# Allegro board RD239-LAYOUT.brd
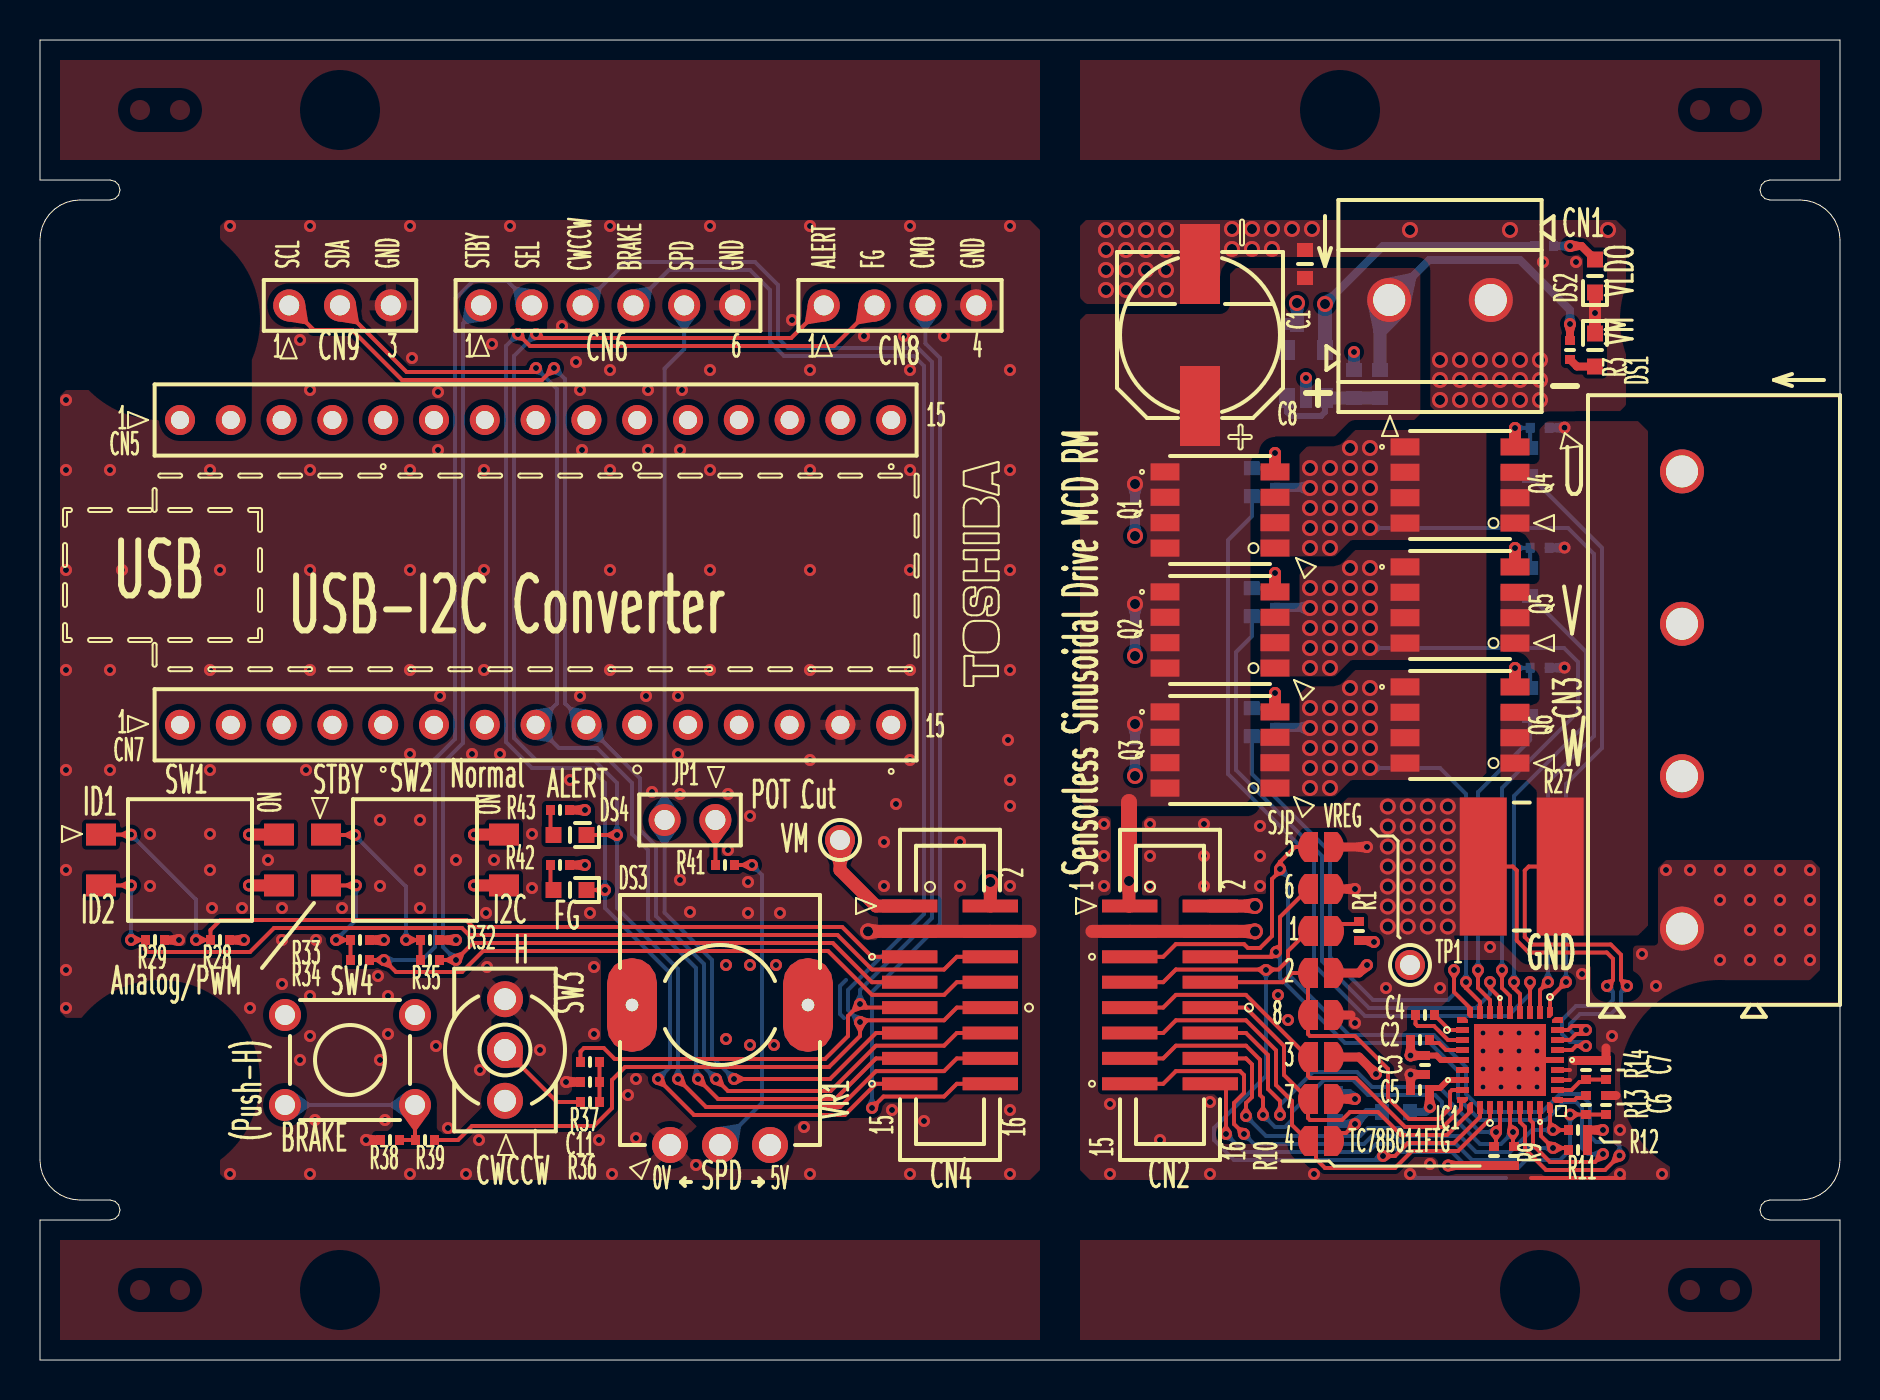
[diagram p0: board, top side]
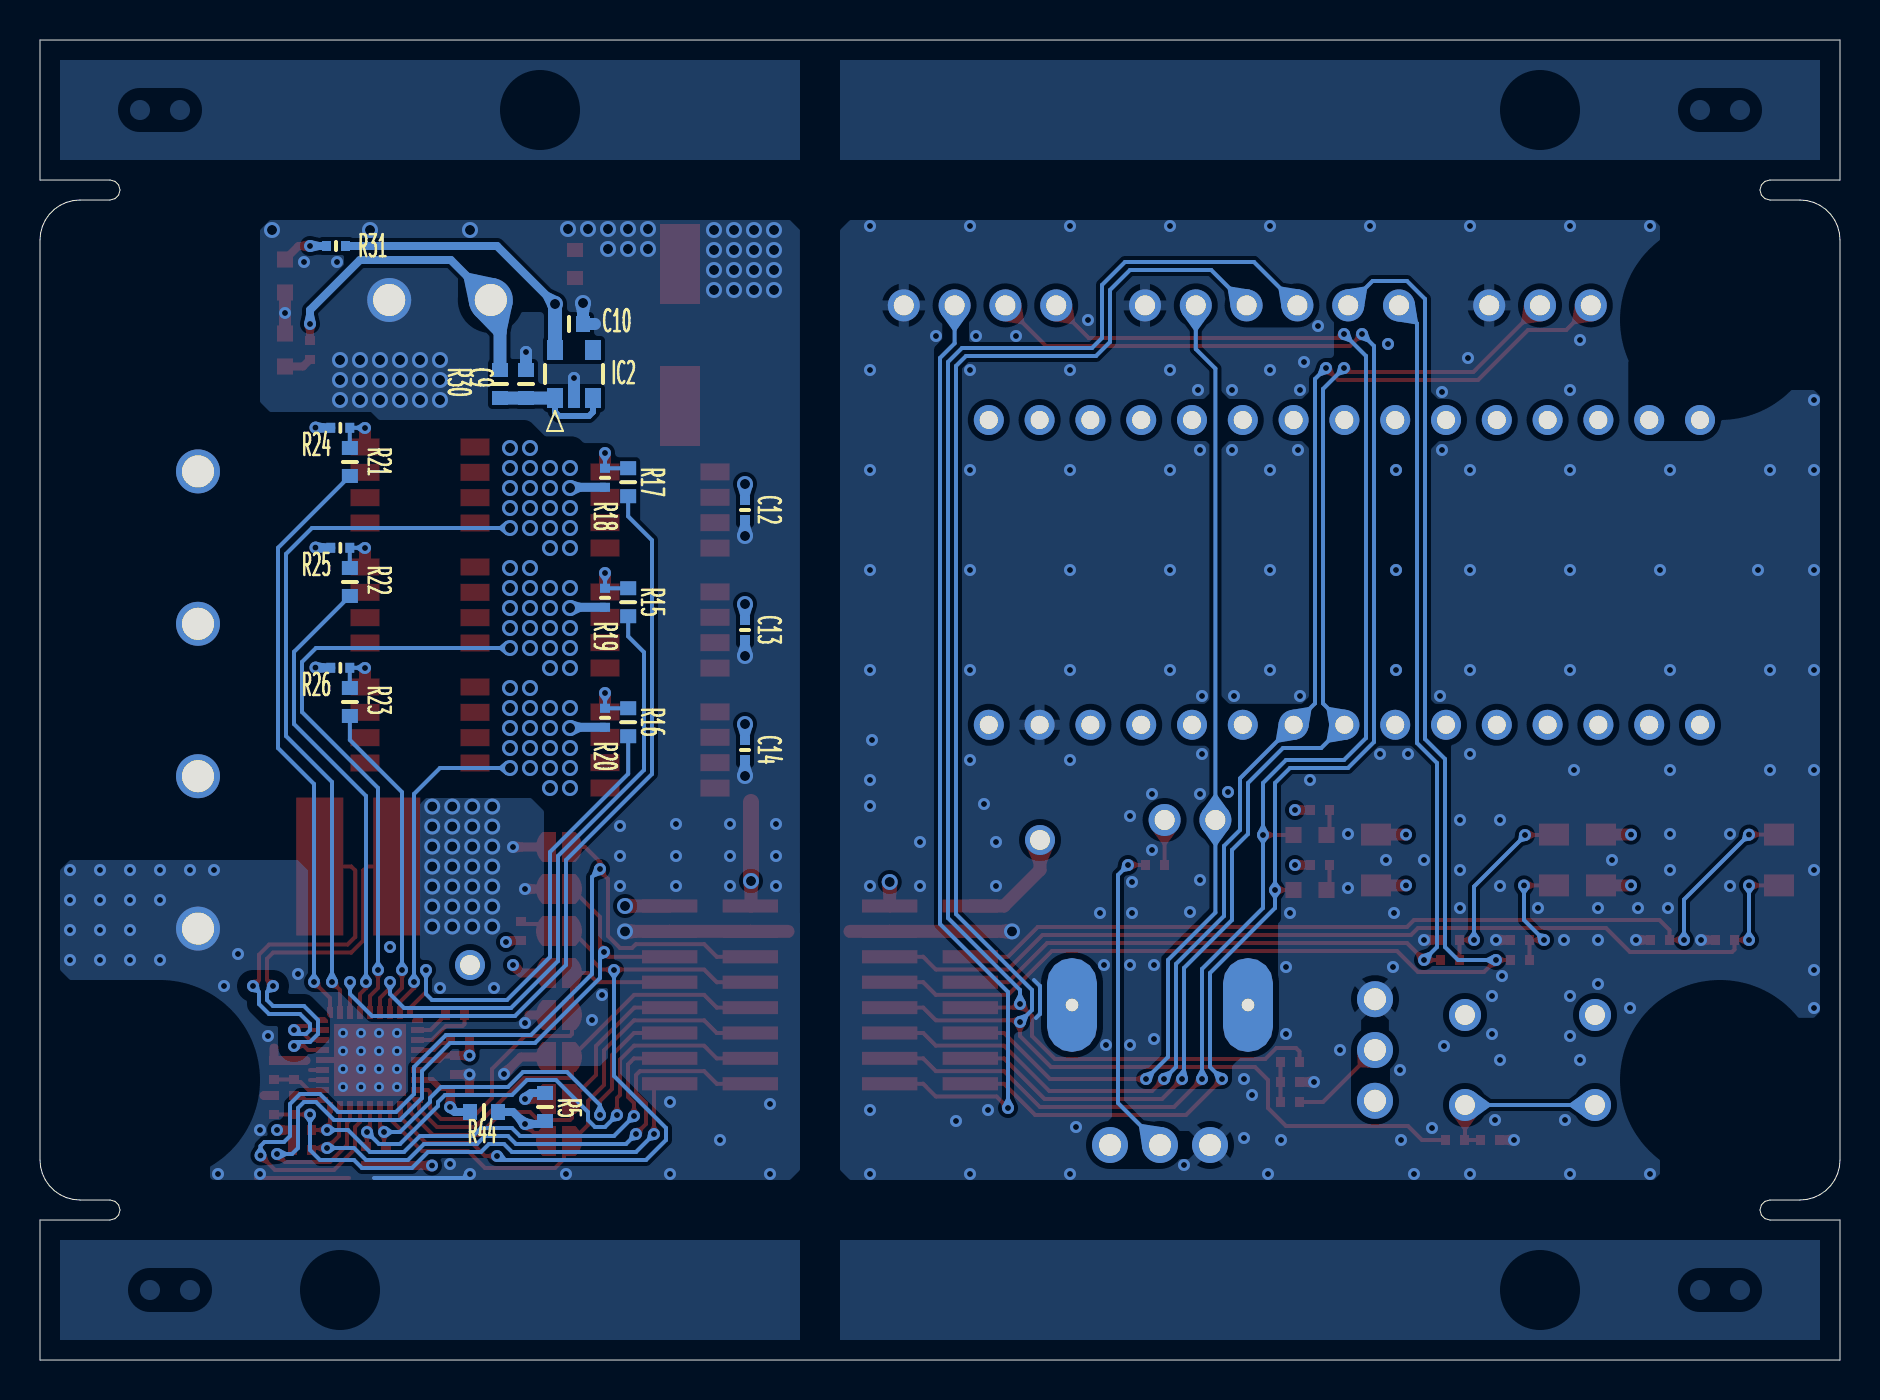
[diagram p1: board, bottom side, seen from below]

Outline 90 x 66 mm; copper layers: TOP, CONDUCTIVE2, CONDUCTIVE3, BOTTOM. Coordinates in mm from the lower left corner of the outline.
Outline path: 0,66 90,66 90,59 86.5,59 86.25,58.93 86.07,58.75 86,58.5 86.07,58.25 86.25,58.07 86.5,58 88,58 88.35,57.97 88.68,57.88 89,57.73 89.29,57.53 89.53,57.29 89.73,57 89.88,56.68 89.97,56.35 90,56 90,10 89.97,9.65 89.88,9.32 89.73,9 89.53,8.71 89.29,8.47 89,8.27 88.68,8.12 88.35,8.03 88,8 86.5,8 86.25,7.93 86.07,7.75 86,7.5 86.07,7.25 86.25,7.07 86.5,7 90,7 90,0 0,0 0,7 3.5,7 3.75,7.07 3.93,7.25 4,7.5 3.93,7.75 3.75,7.93 3.5,8 2,8 1.65,8.03 1.32,8.12 1,8.27 0.71,8.47 0.47,8.71 0.27,9 0.12,9.32 0.03,9.65 0,10 0,56 0.03,56.35 0.12,56.68 0.27,57 0.47,57.29 0.71,57.53 1,57.73 1.32,57.88 1.65,57.97 2,58 3.5,58 3.75,58.07 3.93,58.25 4,58.5 3.93,58.75 3.75,58.93 3.5,59 0,59 0,66

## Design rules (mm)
constraint set DEFAULT: 

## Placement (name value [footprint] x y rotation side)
C1  -  [CHIP1608_GS_1]  63.25 54.8 270 top
C2  -  [CHIP1005_GS_2]  69 16 180 top
C3  -  [CHIP1005_GS_2]  69.25 14.75 90 top
C4  -  [CHIP1005_GS_2]  69.25 17.25 180 top
C5  -  [CHIP1005_GS_2]  69 13.5 0 top
C6  -  [CHIP1005_GS_2]  78.3 12.75 270 top
C7  -  [CHIP1005_GS_2]  78.3 14.5 270 top
C8  -  [AC_S_8X10_2L_PN_A]  58 51.25 0 top
C9  -  [CHIP1608_GS_1]  65.7 48.8 270 bottom
C10  -  [CHIP1608_GS_1]  63.55 51.8 0 bottom
C11  -  [CHIP1005_GS_2]  27.5 13.9 0 top
C12  -  [CHIP1005_GS_2]  54.75 42.5 90 bottom
C13  -  [CHIP1005_GS_2]  54.75 36.5 90 bottom
C14  -  [CHIP1005_GS_2]  54.75 30.5 90 bottom
CN1  -  [TM_I_TB009_508_02_CU_A]  70 53 180 top
CN2  -  [CN_S_3220_16_0300_CNC]  56.5 18.26 270 top
CN3  -  [TM_I_TB005_762_04_CU]  82.1 33 90 top
CN4  -  [CN_S_3220_16_0300_CNC]  45.5 18.26 270 top
CN5  -  [HP_I_6_534237_3_TE]  24.78 47 0 top
CN6  -  [HP_I_M20_99906__HW]  28.4 52.73 0 top
CN7  -  [HP_I_6_534237_3_TE]  24.78 31.76 0 top
CN8  -  [HP_I_M20_99904__HW]  43 52.73 0 top
CN9  -  [HP_I_M20_99903__HW]  15 52.73 0 top
DS1  -  [LD_S_APT1608_KB_A]  77.75 50.5 270 top
DS2  -  [LD_S_APT1608_KB_A]  77.75 54.2 90 top
DS3  -  [LD_S_APT1608_KB_A]  26.5 23.5 180 top
DS4  -  [LD_S_APT1608_KB_A]  26.5 26.25 180 top
IC1  -  [IC_S_QFN_36E_05_GS]  73.5 15 90 top
IC2  -  [IC_S_SOP_5_0_95_TS]  63.3 49.3 180 bottom
JP1  -  [HP_I_M20_99902__HW]  32.5 27 180 top
NOREF  -  []  -13 -22 0 top
NOREF#2  -  []  -13 -18.5 0 top
NOREF#3  -  []  47.9 33.7 90 top
Q1  -  [TR_S_SOP_ADVANCE_TS]  59 42.5 90 top
Q2  -  [TR_S_SOP_ADVANCE_TS]  59 36.5 90 top
Q3  -  [TR_S_SOP_ADVANCE_TS]  59 30.5 90 top
Q4  -  [TR_S_SOP_ADVANCE_TS]  71 43.75 90 top
Q5  -  [TR_S_SOP_ADVANCE_TS]  71 37.75 90 top
Q6  -  [TR_S_SOP_ADVANCE_TS]  71 31.75 90 top
R1  -  [CHIP1005_GS_2]  65.95 21.45 270 top
R3  -  [CHIP1005_GS_2]  76.5 50.5 90 top
R5  -  [CHIP1608_GS_1]  64.75 12.65 270 bottom
R9  -  [CHIP1005_GS_2]  73.7 10.2 270 top
R10  -  [CHIP1005_GS_2]  72.7 10.2 270 top
R11  -  [CHIP1005_GS_2]  76.9 10.5 0 top
R12  -  [CHIP1005_GS_2]  76.9 11.5 0 top
R13  -  [CHIP1005_GS_2]  77.3 12.75 270 top
R14  -  [CHIP1005_GS_2]  77.3 14.5 270 top
R15  -  [CHIP1608_GS_1]  60.59 37.89 90 bottom
R16  -  [CHIP1608_GS_1]  60.59 31.89 90 bottom
R17  -  [CHIP1608_GS_1]  60.59 43.89 90 bottom
R18  -  [CHIP1005_GS_2]  61.75 44.11 90 bottom
R19  -  [CHIP1005_GS_2]  61.75 38.11 90 bottom
R20  -  [CHIP1005_GS_2]  61.75 32.11 90 bottom
R21  -  [CHIP1608_GS_1]  74.51 44.9 90 bottom
R22  -  [CHIP1608_GS_1]  74.51 38.9 90 bottom
R23  -  [CHIP1608_GS_1]  74.51 32.9 90 bottom
R24  -  [CHIP1005_GS_2]  74.99 46.61 180 bottom
R25  -  [CHIP1005_GS_2]  74.99 40.61 0 bottom
R26  -  [CHIP1005_GS_2]  74.99 34.61 180 bottom
R27  -  [R_S_PRL3264_SS]  74.09 24.67 0 top
R28  -  [CHIP1005_GS_2]  9 21 0 top
R29  -  [CHIP1005_GS_2]  5.75 21 0 top
R30  -  [CHIP1608_GS_1]  67 48.8 90 bottom
R31  -  [CHIP1005_GS_2]  75.2 55.7 180 bottom
R32  -  [CHIP1005_GS_2]  19.5 21 0 top
R33  -  [CHIP1005_GS_2]  16 21 0 top
R34  -  [CHIP1005_GS_2]  16 20 180 top
R35  -  [CHIP1005_GS_2]  19.5 20 180 top
R36  -  [CHIP1005_GS_2]  27.5 12.9 180 top
R37  -  [CHIP1005_GS_2]  27.5 14.9 0 top
R38  -  [CHIP1005_GS_2]  17.5 11 0 top
R39  -  [CHIP1005_GS_2]  19.25 11 180 top
R41  -  [CHIP1005_GS_2]  34.25 24.75 0 top
R42  -  [CHIP1005_GS_2]  26 24.75 0 top
R43  -  [CHIP1005_GS_2]  26 27.5 0 top
R44  -  [CHIP1608_GS_1]  67.8 12.4 0 bottom
SJP1  -  [TP_S_SHORTLAND_EC_1_GS_2]  64.05 21.45 0 top
SJP2  -  [TP_S_SHORTLAND_EC_1_GS_2]  64.05 19.35 0 top
SJP3  -  [TP_S_SHORTLAND_EC_1_GS_2]  64.05 15.15 180 top
SJP4  -  [TP_S_SHORTLAND_EC_1_GS_2]  64.05 10.95 180 top
SJP5  -  [TP_S_SHORTLAND_EC_1_GS_2]  64.05 25.65 180 top
SJP6  -  [TP_S_SHORTLAND_EC_1_GS_2]  64.05 23.55 180 top
SJP7  -  [TP_S_SHORTLAND_EC_1_GS_2]  64.05 13.05 180 top
SJP8  -  [TP_S_SHORTLAND_EC_1_GS_2]  64.05 17.25 180 top
SW1  -  [SW_S_DS04_254_2_02BK_SMT_CU]  7.5 25 270 top
SW2  -  [SW_S_DS04_254_2_02BK_SMT_CU]  18.75 25 270 top
SW3  -  [SW_I_2MS1T2B4M2_DW]  23.25 15.5 90 top
SW4  -  [SW_I_6X6TACTILE_GS]  15.5 15 0 top
TP1  -  [TP_I_TH1_0_LC1_5_RC1_6_GS]  68.5 19.75 0 top
VM  -  [TP_I_TH1_0_LC1_5_RC1_6_GS]  40 26 0 top
VR1  -  [VR_I_PTV09A_4020U_B_BO]  34 17.75 0 top

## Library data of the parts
C1 C9 C10 R5 R15-R17 R21-R23 R30 R44 = Chip1608_GS_1
C2-C7 C11-C14 R1 R3 R9-R14 R18-R20 R24-R26 R28 R29 R31-R39 R41-R43 = Chip1005_GS_2
C8 = EEE-FN1V331UP_PN_A
CN1 = TB009-508-02_CU_A
CN2 CN4 = 3220-16-0300_CNC
CN3 = TB005-762-04_CU
CN5 CN7 = 6-534237-3_TE
CN6 = M20-99906**_HW
CN8 = M20-99904**_HW
CN9 = M20-99903**_HW
DS1-DS4 = APT1608_KB_A
IC1 = TC78B011FTG_GS
IC2 = TCR1HF_TS
JP1 = M20-99902**_HW
Q1-Q6 = TPH1R204PB_TS
R27 = PRL3264_SS
SJP1-SJP8 = TP_S_ShortLand_EC-1_GS
SW1 SW2 = DS04-254-2-02BK-SMT_CU
SW3 = 2MS1T2B4M2_DW
SW4 = B3F-1025_GS
TP1 VM = TP_I_TH1.0_LC1.5_RC1.6_GS
VR1 = PTV09A-4020U-B_BO

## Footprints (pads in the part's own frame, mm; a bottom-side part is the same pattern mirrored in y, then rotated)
AC_S_8X10_2L_PN_A
  rect 2x4 smd: 1(0,3.55) 2(0,-3.55)
CHIP1005_GS_2
  rect 0.45x0.5 smd: 1(-0.475,0) 2(0.475,0)
CHIP1608_GS_1
  rect 0.7x0.8 smd: 1(-0.7,0) 2(0.7,0)
CN_S_3220_16_0300_CNC
  rect 0.65x2.77 smd: 1(-4.445,-2.015) 2(-4.445,2.015) 3(-3.175,-2.015) 4(-3.175,2.015) 5(-1.905,-2.015) 6(-1.905,2.015) 7(-0.635,-2.015) 8(-0.635,2.015) 9(0.635,-2.015) 10(0.635,2.015) 11(1.905,-2.015) 12(1.905,2.015) 13(3.175,-2.015) 14(3.175,2.015) 15(4.445,-2.015) 16(4.445,2.015)
HP_I_6_534237_3_TE
  round 1.5 hole 0.9: 1(-17.78,0) 2(-15.24,0) 3(-12.7,0) 4(-10.16,0) 5(-7.62,0) 6(-5.08,0) 7(-2.54,0) 8(0,0) 9(2.54,0) 10(5.08,0) 11(7.62,0) 12(10.16,0) 13(12.7,0) 14(15.24,0) 15(17.78,0)
HP_I_M20_99902__HW
  round 1.6 hole 1: 1(-1.27,0) 2(1.27,0)
HP_I_M20_99903__HW
  round 1.6 hole 1: 1(-2.54,0) 2(0,0) 3(2.54,0)
HP_I_M20_99904__HW
  round 1.6 hole 1: 1(-3.81,0) 2(-1.27,0) 3(1.27,0) 4(3.81,0)
HP_I_M20_99906__HW
  round 1.6 hole 1: 1(-6.35,0) 2(-3.81,0) 3(-1.27,0) 4(1.27,0) 5(3.81,0) 6(6.35,0)
IC_S_QFN_36E_05_GS
  custom 0.075x0.075 smd: 1(-2,-2.375) 9(2,-2.375) 10(2.375,-2) 18(2.375,2) 19(2,2.375) 27(-2,2.375) 28(-2.375,2) 36(-2.375,-2)
  rect 0.3x0.65 smd: 2(-1.5,-2.375) 3(-1,-2.375) 4(-0.5,-2.375) 5(0,-2.375) 6(0.5,-2.375) 7(1,-2.375) 8(1.5,-2.375) 20(1.5,2.375) 21(1,2.375) 22(0.5,2.375) 23(0,2.375) 24(-0.5,2.375) 25(-1,2.375) 26(-1.5,2.375)
  rect 0.65x0.3 smd: 11(2.375,-1.5) 12(2.375,-1) 13(2.375,-0.5) 14(2.375,0) 15(2.375,0.5) 16(2.375,1) 17(2.375,1.5) 29(-2.375,1.5) 30(-2.375,1) 31(-2.375,0.5) 32(-2.375,0) 33(-2.375,-0.5) 34(-2.375,-1) 35(-2.375,-1.5)
  rect 3.6x3.6 smd: 37(0,0)
IC_S_SOP_5_0_95_TS
  rect 0.8x1 smd: 1(-0.95,-1.2) 3(0.95,-1.2) 4(0.95,1.2) 5(-0.95,1.2)
  rect 0.6x1 smd: 2(0,-1.2)
LD_S_APT1608_KB_A
  rect 0.8x0.8 smd: 1(0.825,0) 2(-0.825,0)
R_S_PRL3264_SS
  rect 2.35x6.9 smd: 1(-1.925,0) 2(1.925,0)
SW_I_2MS1T2B4M2_DW
  round 1.8 hole 1.1: 1(-2.54,0) 2(0,0) 3(2.54,0)
SW_I_6X6TACTILE_GS
  round 1.6 hole 1: 1(3.25,-2.25) 2(-3.25,-2.25) 3(3.25,2.25) 4(-3.25,2.25)
SW_S_DS04_254_2_02BK_SMT_CU
  rect 1.1x1.5 smd: 1(-1.27,-4.45) 2(1.27,-4.45) 3(1.27,4.45) 4(-1.27,4.45)
TM_I_TB005_762_04_CU
  round 2.2 hole 1.6: 1(11.43,0) 2(3.81,0) 3(-3.81,0) 4(-11.43,0)
TM_I_TB009_508_02_CU_A
  round 2.2 hole 1.6: 1(2.54,0) 2(-2.54,0)
TP_I_TH1_0_LC1_5_RC1_6_GS
  round 1.5 hole 1: 1(0,0)
TP_S_SHORTLAND_EC_1_GS_2
  custom 0.25x0.25 smd: 1(-0.65,0) 2(0.65,0)
TR_S_SOP_ADVANCE_TS
  rect 0.85x1.45 smd: 1(-1.905,-2.75) 2(-0.635,-2.75) 3(0.635,-2.75) 4(1.905,-2.75) 5(1.905,2.75) 6(0.635,2.75) 7(-0.635,2.75) 8(-1.905,2.75)
VR_I_PTV09A_4020U_B_BO
  round 1.8 hole 1.1: 1(-2.5,-7) 2(0,-7) 3(2.5,-7)
  custom 0.625x0.625 hole 1.9x4.1: 4(-4.4,0) 5(4.4,0)

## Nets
GND: C1.1 C3.1 C5.1 C6.1 C7.1 C8.1 C9.1 C10.1 C12.1 C13.1 C14.1 CN1.2 CN2.3 CN2.4 CN3.4 DS1.2 DS2.2 IC1.3 IC1.4 IC1.5 IC1.6 IC1.37 IC2.2 R5.1 R14.1 R27.1 SJP3.1 SJP5.1 SJP6.1 SJP7.1 SJP8.1
GNDX: C11.1 CN4.3 CN4.4 CN6.6 CN7.14 CN8.4 CN9.3 R28.2 R29.2 R32.2 R33.2 R38.1 SW3.3 VR1.1
ALERT: CN2.14 IC1.36 R12.1
ALERTX: CN4.14 CN8.1 DS4.2
BRAKE: CN2.10 IC1.28 SJP7.2
BRAKEX: CN4.10 CN6.4 R39.1
CMO: C6.2 CN2.16 R13.2
CMOX: CN4.16 CN8.3
CWCCW: CN2.9 IC1.27 SJP3.2
CWCCWX: CN4.9 CN6.3 R37.1
FG: CN2.15 IC1.35 R11.1
FGX: CN4.15 CN8.2 DS3.2
GHU: IC1.12 R17.1
GHV: IC1.15 R15.1
GHW: IC1.18 R16.1
GLU: IC1.10 R21.1
GLV: IC1.13 R22.1
GLW: IC1.16 R23.1
ID1: CN2.5 IC1.33 SJP5.2
ID1X: CN4.5 R28.1 SW1.1
ID2: CN2.6 IC1.34 SJP6.2
ID2X: CN4.6 R29.1 SW1.2
OUTU: CN3.1 IC1.11 Q1.1 Q1.2 Q1.3 Q4.5 Q4.6 Q4.7 Q4.8 R18.1
OUTV: CN3.2 IC1.14 Q2.1 Q2.2 Q2.3 Q5.5 Q5.6 Q5.7 Q5.8 R19.1
OUTW: CN3.3 IC1.17 Q3.1 Q3.2 Q3.3 Q6.5 Q6.6 Q6.7 Q6.8 R20.1
RSA: IC1.7 IC1.8 Q4.1 Q4.2 Q4.3 Q5.1 Q5.2 Q5.3 Q6.1 Q6.2 Q6.3 R24.1 R25.2 R26.1 R27.2
SCL: CN2.12 IC1.31 R10.1
SCLX: CN4.12 CN7.9 CN9.1
SDA: CN2.13 IC1.32 R9.1
SDAX: CN4.13 CN7.8 CN9.2
SEL: CN2.8 IC1.26 SJP2.1 SJP8.2
SELX: CN4.8 CN6.2 R34.1
SPD: CN2.11 IC1.30 SJP4.2
SPDX: CN4.11 CN6.5 JP1.2
STBY: CN2.7 IC1.29 SJP1.1
STBYX: CN4.7 CN6.1 R35.1
VLDO: C10.2 CN2.2 IC2.5 R1.2 R31.2
VLDOX: CN4.2 R42.2 R43.2 SW1.3 SW1.4 SW2.3 SW2.4 SW3.1 SW4.3 SW4.4 VR1.3
VM: C1.2 C2.2 C3.2 C8.2 C12.2 C13.2 C14.2 CN1.1 CN2.1 IC1.23 Q1.5 Q1.6 Q1.7 Q1.8 Q2.5 Q2.6 Q2.7 Q2.8 Q3.5 Q3.6 Q3.7 Q3.8 R3.2 R30.2
VMX: CN4.1 VM.1
VREG: C5.2 IC1.25 R9.2 R10.2 R11.2 R12.2 R44.2 SJP2.2 TP1.1
N00000: CN5.1
N73073: C4.1 IC1.20
N73078: C4.2 IC1.21
N73366: C7.2 IC1.2 R14.2
N87798: Q1.4 R17.2 R18.2
N87832: Q2.4 R15.2 R19.2
N87866: Q3.4 R16.2 R20.2
N88470: Q5.4 R22.2 R25.1
N88482: Q6.4 R23.2 R26.2
N88708: Q4.4 R21.2 R24.2
N99829: C2.1 IC1.22
N100688: IC1.1 R13.1
N145122: R1.1 SJP1.2
N153811: R32.1 R35.2 SW2.1
N153813: R33.1 R34.2 SW2.2
N153829: C11.2 R36.1 R37.2
N153845: R38.2 R39.2 SW4.1 SW4.2
N153865: R41.2 VR1.2
N153867: JP1.1 R41.1
N157910: R5.2 R44.1 SJP4.1
N213336: R36.2 SW3.2
N213555: DS1.1 R3.1
N213849: DS3.1 R42.1
N213908: DS4.1 R43.1
N228706: C9.2 IC2.1 IC2.3 R30.1
N228786: DS2.1 R31.1

Pads without a net: CN5 2 3 4 5 6 7 8 9 10 11 12 13 14 15; CN7 1 2 3 4 5 6 7 10 11 12 13 15; IC1 9 19 24; IC2 4; VR1 4 5

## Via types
v1: diameter 0.6, hole 0.3, TOP to BOTTOM, 311 vias
v2: diameter 0.8, hole 0.5, TOP to BOTTOM, 146 vias
v3: diameter 0.5, hole 0.25, TOP to BOTTOM, 16 vias

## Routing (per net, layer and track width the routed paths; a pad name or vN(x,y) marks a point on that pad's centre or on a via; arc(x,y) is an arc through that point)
GND: length 59.5
  TOP w0.2: 75.92,14.5 76.5,14.5 ; 74.55,9.1 79.2,9.1 ; 75.92,14 76.5,14 ; 75.92,15.5 76.6,15.5 76.8,15.7 v1(77.3,15.7) ; v1(78.35,18.7) 78.65,19 78.65,20.06 78.34,20.37 74.44,20.37 73.84,20.97 73.84,24.47 73.64,24.67 R27.1
  TOP w0.3: 75.04,15 IC1.5 75.92,15
  TOP w0.45: SJP5.1 v1(66.35,25.65) ; 65.55,17.25 SJP8.1 ; SJP3.1 65.95,15.15 v1(66.8,14.3) ; 76.7,14.97 R14.1 C7.1 78.3,15.6 ; C6.1 78.8,13.22 ; SJP7.1 v1(65.75,13.05) ; C5.1 v1(68.53,14.28) C3.1 ; SJP6.1 v1(65.75,23.55)
  TOP w0.6: DS2.2 v1(77.75,52.35) DS1.2
  TOP w0.65: 52.6,21.43 CN2.3 CN2.4 v2(60.75,21.43)
  BOTTOM w0.2: v1(78.35,18.7) 78.65,18.4 78.65,18 78.35,17.7 76.8,17.7 76.1,17 76.1,16.3 76.5,15.9 77,15.9 v1(77.3,15.7) ; 73.3,9.1 68.8,9.1 v1(68.5,9.3)
  BOTTOM w0.4: v1(65.75,13.05) 65.45,13.35 R5.1
  BOTTOM w0.45: C12.1 v2(54.75,41.2) ; C13.1 v2(54.75,35.2) ; C14.1 v2(54.75,29.2)
  BOTTOM w0.6: v2(62.85,52.85) C10.1 62.25,51.8 ; IC2.2 v1(63.3,49.1) ; C9.1 v1(65.7,50.4)
  vias: v1(53.2,26.8) v1(53.2,25.2) v1(53.2,23.7) v1(53.5,12.8) v1(53.5,9.3) v1(55.5,26.8) v1(55.5,25.2) v1(55.5,23.7) v1(56,11) v1(58.2,26.8) v1(58.2,25.2) v1(58.2,23.7) v1(58.5,12.9) v1(58.5,9.3) v1(61,26.7) v1(61,25.2) v1(61,23.7) v1(61.9,18.25) v1(62.4,17) v1(63.7,9.3) v1(65.75,16.85) v1(67.3,18.6) v1(69.5,9.8) v1(70,18.6) v1(72.5,20.65) v1(75.15,54.9) v1(76.8,54.9) v1(77.1,19.3) v1(78.6,16.2) v1(79,11.5) v1(79,9.3) v1(80.1,20.3) v1(80.8,18.7) v1(81.1,9.3) v1(81.3,24.5) v1(82.5,24.5) v1(84,24.5) v1(84,23) v1(84,20) v1(85.5,24.5) v1(85.5,23) v1(85.5,21.5) v1(85.5,20) v1(87,24.5) v1(87,23) v1(87,21.5) v1(87,20) v1(88.5,24.5) v1(88.5,23) v1(88.5,21.5) v1(88.5,20) v2(53.3,56.5) v2(53.3,55.5) v2(53.3,54.5) v2(53.3,53.5) v2(54.3,56.5) v2(54.3,55.5) v2(54.3,54.5) v2(54.3,53.5) v2(55.3,56.5) v2(55.3,55.5) v2(55.3,54.5) v2(55.3,53.5) v2(56.3,56.5) v2(56.3,55.5) v2(56.3,54.5) v2(56.3,53.5) v2(59.6,56.55) v2(59.6,55.55) v2(60.6,56.55) v2(60.6,55.55) v2(61.6,56.55) v2(61.6,55.55) v2(62.6,56.55) v2(63.6,56.55) v2(67.39,27.67) v2(67.39,26.67) v2(67.39,25.67) v2(67.39,24.67) v2(67.39,23.67) v2(67.39,22.67) v2(67.39,21.67) v2(68.39,27.67) v2(68.39,26.67) v2(68.39,25.67) v2(68.39,24.67) v2(68.39,23.67) v2(68.39,22.67) v2(68.39,21.67) v2(68.5,56.5) v2(69.39,27.67) v2(69.39,26.67) v2(69.39,25.67) v2(69.39,24.67) v2(69.39,23.67) v2(69.39,22.67) v2(69.39,21.67) v2(70,50) v2(70,49) v2(70,48) v2(70.39,27.67) v2(70.39,26.67) v2(70.39,25.67) v2(70.39,24.67) v2(70.39,23.67) v2(70.39,22.67) v2(70.39,21.67) v2(71,50) v2(71,49) v2(71,48) v2(72,50) v2(72,49) v2(72,48) v2(73,50) v2(73,49) v2(73,48) v2(73.5,56.5) v2(74,50) v2(74,49) v2(74,48) v2(75,50) v2(75,49) v2(75,48) v2(78.4,56.5) v3(72.15,16.35) v3(72.15,15.45) v3(72.15,14.55) v3(72.15,13.65) v3(73.05,16.35) v3(73.05,15.45) v3(73.05,14.55) v3(73.05,13.65) v3(73.95,16.35) v3(73.95,15.45) v3(73.95,14.55) v3(73.95,13.65) v3(74.85,16.35) v3(74.85,15.45) v3(74.85,14.55) v3(74.85,13.65)
GNDX: length 15.5
  TOP w0.45: R38.1 v1(16.3,11) ; R28.2 v1(10.2,21) ; C11.1 v1(26.3,13.9) ; R32.2 v1(20.8,21) ; R33.2 v1(17.2,21) ; R29.2 v1(6.95,21)
  TOP w0.65: v2(41.4,21.43) CN4.3 CN4.4 49.5,21.43
  CONDUCTIVE3 w0.2: 22.85,14.25 23.7,14.25
  BOTTOM w0.2: 40.2,17.1 40,17.3 40,18.7 40.3,19
  vias: v1(1.3,48) v1(1.3,44.5) v1(1.3,39.5) v1(1.3,34.5) v1(1.3,29.5) v1(1.3,24.5) v1(1.3,19.5) v1(1.3,17.6) v1(3.5,44.5) v1(3.5,34.5) v1(3.5,29.5) v1(4.1,39.5) v1(5.5,26.3) v1(5.5,23.7) v1(8.5,44.5) v1(8.5,34.5) v1(8.5,29.5) v1(8.5,26.3) v1(8.5,24.5) v1(8.6,22.6) v1(9,39.5) v1(9.5,56.7) v1(9.5,9.3) v1(10.1,22.6) v1(10.5,17.6) v1(11.4,25) v1(12.1,22.6) v1(12.1,21) v1(12.1,18.8) v1(13,51) v1(13,15) v1(13.3,29.5) v1(13.5,56.7) v1(13.5,48.5) v1(13.5,44.5) v1(13.5,39.5) v1(13.5,34.5) v1(13.5,18.2) v1(13.5,16.2) v1(13.5,9.3) v1(13.8,21) v1(13.75,12) v1(15.1,22.6) v1(16.9,19.2) v1(17,27) v1(17,23.7) v1(17,15) v1(17.25,12) v1(17.4,18.2) v1(17.4,16.3) v1(18.5,56.7) v1(18.5,44.5) v1(18.5,39.5) v1(18.5,34.5) v1(18.5,30.3) v1(18.5,9.3) v1(18.6,50.1) v1(19,27) v1(19,24.5) v1(19,22.6) v1(19.8,15.7) v1(19.9,48.4) v1(19.9,45.5) v1(20,33.2) v1(20.4,11.6) v1(20.8,25) v1(21.3,9.3) v1(21.6,30.3) v1(21.95,11) v1(22,14.5) v1(22.2,44.5) v1(22.2,39.5) v1(22.2,34.5) v1(22.3,22.35) v1(22.35,19.65) v1(22.6,50.8) v1(22.7,25) v1(23,30.3) v1(23.5,56.7) v1(24.6,26.3) v1(24.6,23.6) v1(25,15.5) v1(26.1,51.7) v1(26.5,29) v1(26.8,49.9) v1(27,48.5) v1(27,33.2) v1(27.1,45.5) v1(27.5,22.35) v1(27.7,19.65) v1(27.7,16.3) v1(27.95,11) v1(28.5,56.7) v1(28.5,49.5) v1(28.5,44.5) v1(28.5,39.5) v1(28.5,34.5) v1(28.6,9.3) v1(29.4,13.25) v1(29.8,14.05) v1(29.8,11.1) v1(30.3,33.2) v1(30.4,48.5) v1(30.4,45.5) v1(30.6,28.4) v1(31.9,33.2) v1(31.9,30.3) v1(32,45.5) v1(32,28.3) v1(32,24) v1(32.1,48.5) v1(32.5,22.4) v1(32.8,9.75) v1(33.5,56.7) v1(33.5,49.5) v1(33.5,44.5) v1(33.5,39.5) v1(33.5,34.5) v1(34.3,19.75) v1(34.3,16.05) v1(34.4,28.3) v1(34.4,25.5) v1(35.4,23.9) v1(35.4,22.35) v1(35.5,27.2) v1(35.5,19.75) v1(35.5,15.75) v1(36.7,15.75) v1(36.8,19.75) v1(37,22.35) v1(37.6,52) v1(38.2,11.65) v1(38.5,56.7) v1(38.5,49.5) v1(38.5,44.5) v1(38.5,39.5) v1(38.5,34.5) v1(38.5,30) v1(38.5,9.3) v1(41.2,51.2) v1(42.2,25.9) v1(42.2,23.7) v1(42.6,12.5) v1(42.8,27.8) v1(43.2,51.2) v1(43.5,56.7) v1(43.5,49.5) v1(43.5,44.5) v1(43.5,39.5) v1(43.5,34.5) v1(43.5,30) v1(43.5,9.3) v1(44.2,11.95) v1(45.2,51.2) v1(46,25.9) v1(46,23.7) v1(48.4,31) v1(48.5,56.7) v1(48.5,49.5) v1(48.5,44.5) v1(48.5,39.5) v1(48.5,34.5) v1(48.5,29) v1(48.5,27.7) v1(48.5,23.7) v1(48.5,12.5) v1(48.5,9.3)
ALERT: length 23.7
  TOP w0.2: 76.42,11.5 v1(75.65,11.5) 75.5,11.83 75.5,12.57 ; v1(60.3,12.2) 60.3,12.85 60.6,13.15 60.6,14.78 60.3,15.08 CN2.14
  BOTTOM w0.2: v1(75.65,11.5) 74.6,11.5 73.5,10.4 71.8,10.4 71,11.2 68.35,11.2 67.95,11.6 66.4,11.6 66,11.2 61.3,11.2 v1(60.3,12.2)
ALERTX: length 76.7
  TOP w0.2: CN8.1 37.56,51.1 25.1,51.1 v1(24.8,51.3) ; DS4.2 v1(28.85,26.25) ; v1(31.9,14.05) 33.3,12.65 40.01,12.65 41.8,14.45 45.2,14.45 45.84,15.08 CN4.14
  BOTTOM w0.2: v1(24.8,51.3) 23.7,50.2 23.7,31.1 24.8,30 27.7,30 28.85,28.85 v1(28.85,26.25) 28.85,22.6 31.9,19.55 v1(31.9,14.05)
BRAKE: length 18
  TOP w0.2: CN2.10 60.28,17.62 62.2,15.7 62.2,14.25 SJP7.2 63.4,12.1 63.5,12 65.1,12 65.5,12.4 66.9,12.4 68.05,11.25 70.35,11.25 71.5,12.4 71.5,12.57
BRAKEX: length 85.1
  TOP w0.2: R39.1 20.9,11 21.6,11.7 27.7,11.7 28.6,12.6 28.6,14 29.25,14.65 39.45,14.65 41,16.2 v1(41,16.9) 41.35,16.98 45.2,16.98 45.84,17.62 CN4.10
  BOTTOM w0.2: CN6.4 31.44,54.5 35.5,54.5 36.5,53.5 36.5,50.9 37.2,50.2 43.7,50.2 44.2,49.7 44.2,22.3 40.4,18.5 40.4,17.5 v1(41,16.9)
CMO: length 25.5
  TOP w0.2: v1(76.5,12.28) R13.2 C6.2 ; v1(59.3,11.3) 59.3,13.81 CN2.16
  BOTTOM w0.2: v1(59.3,11.3) 60.2,10.4 66.4,10.4 66.8,10.8 67.55,10.8 67.95,10.4 70.6,10.4 71.4,9.6 73.9,9.6 74.3,10 76,10 76.5,10.5 v1(76.5,12.28)
CMOX: length 48.3
  TOP w0.2: CN4.16 45.84,13.81 45.2,13.18 42.17,13.18 v1(41.6,12.6)
  BOTTOM w0.2: CN8.3 44.27,50.83 45,50.1 45,21.8 41.6,18.4 v1(41.6,12.6)
CWCCW: length 21
  TOP w0.2: 71.08,13 71.05,12.97 71.05,12.55 70.15,11.65 68.25,11.65 65.8,14.1 63.5,14.1 63.4,14.2 SJP3.2 60.3,18.26 56.8,18.26 56.16,17.62 CN2.9
CWCCWX: length 74.5
  TOP w0.2: CN4.9 41.31,17.62 v1(41,17.8) 40.4,17.2 40.4,16.2 39.25,15.05 28.74,15.05 28.19,15.6 27.2,15.6 27.02,15.43 27.02,15
  BOTTOM w0.2: v1(41,17.8) 41,18.5 44.6,22.1 44.6,49.9 43.9,50.6 37.4,50.6 36.9,51.1 36.9,53.75 35.75,54.9 29.3,54.9 CN6.3
FG: length 29
  TOP w0.2: 75,12.57 75,12.05 75.05,12 75.05,11.2 v1(75.65,10.6) 76.33,10.6 76.42,10.5 ; v1(60.2,11.3) 59.7,11.8 59.7,12.85 60.2,13.35 60.2,14.25 60,14.45 56.8,14.45 56.16,13.81 CN2.15
  BOTTOM w0.2: v1(75.65,10.6) 74.3,10.6 73.7,10 71.6,10 70.8,10.8 68.15,10.8 67.75,11.2 66.6,11.2 66.2,10.8 60.7,10.8 v1(60.2,11.3)
FGX: length 76.7
  TOP w0.2: v1(30.9,14.05) 32.7,12.25 40.24,12.25 41.8,13.81 CN4.15 ; DS3.2 v1(28.25,23.5) ; v1(23.9,51.3) 24.5,50.7 39.7,50.7 CN8.2
  BOTTOM w0.2: v1(23.9,51.3) 23.3,50.7 23.3,30.9 24.6,29.6 27.5,29.6 28.25,28.85 v1(28.25,23.5) 28.25,22.6 31.5,19.35 31.5,14.65 v1(30.9,14.05)
GHU: length 40.1
  TOP w0.2: 74.5,17.43 v1(74.5,18.9)
  BOTTOM w0.2: v1(74.5,18.9) 74.5,18.3 73.4,17.2 66.25,17.2 63.7,19.75 63.7,25 59.4,29.3 59.4,40.99 60.59,42.18 60.59,43.19
GHV: length 31.3
  TOP w0.2: 73,17.43 73,18.1 72.5,18.6 v1(72.5,18.9)
  BOTTOM w0.2: v1(72.5,18.9) 72.5,18.3 71.8,17.6 66.45,17.6 64.1,19.95 64.1,25.2 59.8,29.5 59.8,35.39 60.59,36.18 R15.1
GHW: length 23.5
  TOP w0.2: 71.5,17.43 71.5,17.6 70.7,18.4 v1(70.7,19.5)
  BOTTOM w0.2: v1(70.7,19.5) 70.7,18.3 70.4,18 66.65,18 64.5,20.15 64.5,25.4 60.59,29.31 R16.1
GLU: length 29.3
  TOP w0.2: v1(76.3,18.9) 75.5,18.1 75.5,17.43
  BOTTOM w0.2: v1(76.3,18.9) 76.3,28.8 78.1,30.6 78.1,40.61 R21.1
GLV: length 23.5
  TOP w0.2: 74,17.43 74,18.3 73.7,18.6 v1(73.7,18.9)
  BOTTOM w0.2: R22.1 77.3,35.41 77.3,31.8 73.7,28.2 v1(73.7,18.9)
GLW: length 16.1
  TOP w0.2: 72.5,17.43 72.5,18 71.9,18.6 v1(71.9,19.5)
  BOTTOM w0.2: v1(71.9,19.5) 71.9,28.39 74.51,31 R23.1
ID1: length 49.4
  TOP w0.2: CN2.5 56.16,20.16 56.8,20.8 60.2,20.8 60.4,20.6 61,20.6 61.6,21.2 61.6,24.05 61.8,24.25 v1(62,24.55) 62,24.9 62.75,25.65 SJP5.2 ; v1(78.97,10.22) 78.25,9.5 75.3,9.5 74.25,10.55 74.25,11.65 74,11.9 74,12.57
  BOTTOM w0.2: v1(78.97,10.22) 78.97,10.7 78.78,10.9 77.8,10.9 77.5,11.2 77.5,12.8 77,13.3 76,13.3 75.1,12.4 72.2,12.4 71.3,13.3 71.3,14.65 69.7,16.25 65.45,16.25 62.4,19.3 62.4,24.15 v1(62,24.55)
ID1X: length 45.3
  TOP w0.2: CN4.5 41.6,20.16 40.11,21.65 21.65,21.65 21.3,22 9.03,22 8.53,21.5 R28.1 v1(7.8,21) ; SW1.1 v1(4.55,26.27)
  BOTTOM w0.2: v1(4.55,26.27) 7.8,23.02 v1(7.8,21)
ID2: length 36.9
  TOP w0.2: SJP6.2 62,22.15 62,20.7 v1(61.8,20.4) 61.56,20.16 CN2.6 ; 74.5,12.57 74.5,12 74.65,11.85 74.65,10.75 75.5,9.9 77.75,9.9 v1(78.15,10.3)
  BOTTOM w0.2: v1(61.8,20.4) 62,20.1 62,19.1 65.25,15.85 69.5,15.85 70.9,14.45 70.9,13.1 72,12 75.3,12 76.2,12.9 76.8,12.9 77.1,12.6 77.1,10.6 77.4,10.3 v1(78.15,10.3)
ID2X: length 49.3
  TOP w0.2: CN4.6 45.84,20.16 45.2,19.52 41.6,19.52 39.88,21.25 21.45,21.25 21.1,21.6 11.7,21.6 10.5,20.4 5.4,20.4 5.28,20.52 R29.1 v1(4.55,21) ; SW1.2 v1(4.55,23.73)
  BOTTOM w0.2: v1(4.55,21) v1(4.55,23.73)
OUTU: length 37.5
  TOP w0.2: 75,17.43 75,18.5 v1(75.4,18.9)
  BOTTOM w0.2: v2(66.5,41.6) 76.4,41.6 77.7,40.3 77.7,31.2 75.4,28.9 v1(75.4,18.9)
  BOTTOM w0.45: R18.1 63.03,43.64 63.5,43.6
  vias: v2(63.5,44.6) v2(63.5,43.6) v2(63.5,42.6) v2(63.5,41.6) v2(63.5,40.6) v2(64.5,44.6) v2(64.5,43.6) v2(64.5,42.6) v2(64.5,41.6) v2(64.5,40.6) v2(65.5,45.6) v2(65.5,44.6) v2(65.5,43.6) v2(65.5,42.6) v2(65.5,41.6) v2(66.5,45.6) v2(66.5,44.6) v2(66.5,43.6) v2(66.5,42.6)
OUTV: length 31.7
  TOP w0.2: 73.5,17.43 73.5,18.2 73.1,18.6 v1(73.1,19.5)
  BOTTOM w0.2: v2(66.5,35.6) 76.2,35.6 76.9,34.9 76.9,32.4 73.1,28.6 v1(73.1,19.5)
  BOTTOM w0.45: R19.1 63.02,37.63 v2(63.5,37.6)
  vias: v2(63.5,38.6) v2(63.5,36.6) v2(63.5,35.6) v2(63.5,34.6) v2(64.5,38.6) v2(64.5,37.6) v2(64.5,36.6) v2(64.5,35.6) v2(64.5,34.6) v2(65.5,39.6) v2(65.5,38.6) v2(65.5,37.6) v2(65.5,36.6) v2(65.5,35.6) v2(66.5,39.6) v2(66.5,38.6) v2(66.5,37.6) v2(66.5,36.6)
OUTW: length 18.3
  TOP w0.2: v1(71.3,18.9) 71.3,18.6 72,17.9 72,17.43
  BOTTOM w0.2: v1(71.3,18.9) 71.3,28.3 70,29.6 v2(66.5,29.6)
  BOTTOM w0.45: R20.1 63.02,31.63 v2(63.5,31.6)
  vias: v2(63.5,32.6) v2(63.5,30.6) v2(63.5,29.6) v2(63.5,28.6) v2(64.5,32.6) v2(64.5,31.6) v2(64.5,30.6) v2(64.5,29.6) v2(64.5,28.6) v2(65.5,33.6) v2(65.5,32.6) v2(65.5,31.6) v2(65.5,30.6) v2(65.5,29.6) v2(66.5,33.6) v2(66.5,32.6) v2(66.5,31.6) v2(66.5,30.6)
RSA: length 22.7
  TOP w0.2: 75.92,16 76.5,16 76.8,16.3 77,16.3 v1(77.3,16.5) 77,16.7 76.6,16.7 76.4,16.5 75.92,16.5 ; v1(79.35,18.7) 79.05,19 79.05,20.26 78.54,20.77 74.62,20.77 74.24,21.15 74.24,24.47 74.44,24.67 R27.2
  BOTTOM w0.2: v1(79.35,18.7) 79.05,18.4 79.05,17.8 78.55,17.3 77,17.3 76.5,16.8 76.5,16.5 76.7,16.3 77,16.3 v1(77.3,16.5)
  BOTTOM w0.45: v1(76.23,34.62) 75.87,34.61 R26.1 ; v1(76.23,46.62) 75.87,46.61 R24.1 ; R25.2 75.87,40.61 v1(76.23,40.62)
SCL: length 21.9
  TOP w0.2: v1(62,12.25) 62,12.95 61.4,13.55 61.4,15.25 60.3,16.35 CN2.12 ; R10.1 72.8,10.78 v1(72.8,11.4) 73,11.7 73,12.57
  BOTTOM w0.2: v1(62,12.25) 62,12.75 63.65,14.4 65.85,14.4 66.6,13.65 69.95,13.65 70.5,13.1 70.5,12.9 72,11.4 v1(72.8,11.4)
SCLX: length 69.1
  TOP w0.2: v1(25.7,49.6) 25.1,49 18.1,49 15.6,51.5 13.69,51.5 CN9.1 ; v1(33.8,14.05) 34.4,13.45 39.53,13.45 41.8,15.71 45.2,15.71 45.84,16.35 CN4.12
  BOTTOM w0.2: v1(33.8,14.05) 33.2,14.65 33.2,19.8 30.8,22.2 30.8,25.7 30,26.5 30,29.08 CN7.9 26.25,32.83 26.25,49.05 v1(25.7,49.6)
SDA: length 27.5
  TOP w0.2: v1(61.15,12.25) 61.15,13.1 61,13.25 61,15.02 60.3,15.71 56.8,15.71 56.16,15.08 CN2.13 ; 73.5,12.57 73.5,11.73 v1(73.65,11.4) 73.65,10.72 R9.1
  BOTTOM w0.2: v1(73.65,11.4) 73.05,10.8 72,10.8 70.1,12.7 70.1,12.9 69.75,13.25 66.4,13.25 65.65,14 64.2,14 62.6,12.4 62.6,12 62.25,11.65 61.75,11.65 v1(61.15,12.25)
SDAX: length 64
  TOP w0.2: v1(24.8,49.6) 24.5,49.4 18.33,49.4 CN9.2 ; CN4.13 41.8,15.08 39.77,13.05 33.9,13.05 v1(32.9,14.05)
  BOTTOM w0.2: v1(24.8,49.6) 25.85,48.55 25.85,32.83 CN7.8 25.94,30.6 27.85,30.6 29.6,28.85 29.6,26.3 30.4,25.5 30.4,22 32.8,19.6 32.8,14.5 v1(32.9,14.05)
SEL: length 19.5
  TOP w0.2: 71.08,13.5 70.6,13.5 70.5,13.4 70.5,12.6 69.95,12.05 68.45,12.05 67.4,13.1 67.4,14.55 65.75,16.2 63.5,16.2 63.4,16.3 SJP8.2 SJP2.1 62.6,19.35 62.14,18.89 CN2.8
SELX: length 73.2
  TOP w0.2: R34.1 v1(17.2,20) 17.8,19.4 21.1,19.4 22.15,20.45 39.41,20.45 41.6,18.26 45.2,18.26 45.84,18.89 CN4.8
  BOTTOM w0.2: CN6.2 23.37,53.95 21.65,53.95 20.75,53.05 20.75,31.05 19.75,30.05 19.75,20.65 19.1,20 v1(17.2,20)
SPD: length 24.9
  TOP w0.2: 72.5,12.57 72.5,12.05 70.9,10.45 68.6,10.45 67.75,9.6 64.25,9.6 63.8,10.05 63.8,10.55 SJP4.2 62.6,11.75 62.6,12.95 61.8,13.75 61.8,15.48 60.3,16.98 56.8,16.98 56.16,16.35 CN2.11
SPDX: length 50.3
  TOP w0.2: v1(34.7,14.05) 39.5,14.05 41.8,16.35 CN4.11
  BOTTOM w0.2: CN6.5 32.21,50.55 31.23,49.57 JP1.2 31.23,22.37 33.6,20 33.6,15.15 v1(34.7,14.05)
STBY: length 34.8
  TOP w0.2: SJP1.1 62.4,20.45 62.4,20 61.92,19.52 61.66,19.52 v1(61.3,19.5) 60.94,19.52 56.8,19.52 56.16,18.89 CN2.7 ; v1(67.15,10.2) 67.75,10.2 68.4,10.85 70.7,10.85 72,12.15 72,12.57
  BOTTOM w0.2: v1(67.15,10.2) 66.75,10 59.7,10 58.7,11 58.7,11.6 61.3,14.2 v1(61.3,19.5)
STBYX: length 58.5
  TOP w0.2: R35.1 v1(20.8,20) 21.65,20.85 39.64,20.85 41.6,18.89 CN4.7
  BOTTOM w0.2: CN6.1 21.15,51.83 21.15,30.85 20.15,29.85 20.15,20.65 v1(20.8,20)
VLDO: length 57.9
  TOP w0.45: v1(66.7,20.9) 66.35,20.98 R1.2
  TOP w0.65: CN2.2 v2(60.75,22.7)
  CONDUCTIVE3 w0.8: v2(64.25,52.8) 57.5,46.05 57.5,29.1 59.6,27 59.6,23.8 60.7,22.7 v2(60.75,22.7) 61.45,22.7 63.25,20.9 v1(66.7,20.9)
  BOTTOM w0.4: v2(64.25,52.8) 67.15,55.7 74.7,55.7
  BOTTOM w0.7: v2(64.25,52.8) C10.2 IC2.5
VLDOX: length 96.1
  TOP w0.45: R42.2 v1(27.25,24.75) ; R43.2 v1(27.25,27.5)
  TOP w0.6: SW1.4 v1(10.45,26.27) ; SW1.3 v1(10.45,23.73) ; SW2.4 v1(21.7,26.27) ; SW2.3 v1(21.7,23.73)
  TOP w0.65: CN4.2 v2(47.52,23.9)
  CONDUCTIVE3 w0.8: 21,28 19.97,28 ; 21,28 26.75,28 v1(27.25,27.5) v1(27.25,24.75) ; 21,28 21,26.97 ; 19.97,28 21,26.97 ; 19.97,28 12.18,28 v1(10.45,26.27) v1(10.45,23.73) 11.1,23.08 11.1,18.4 SW4.4 SW4.3 20.4,17.25 21,16.65 21,13.5 21.54,12.96 SW3.1 24.84,12.96 25.45,12.35 34.9,12.35 VR1.3 44.4,10.75 45.5,11.85 45.5,21.88 v2(47.52,23.9) ; 21,26.97 v1(21.7,26.27) v1(21.7,23.73)
VM: length 46.2
  TOP w0.3: 71.08,15 70.05,15 69.83,15.22 C3.2
  TOP w0.4: R3.2 v1(76.5,51.8)
  TOP w0.45: C3.2 v1(68.53,15.22) C2.2
  TOP w0.65: v2(54.45,23.95) 54.45,22.7 CN2.1
  TOP w0.8: v2(54.45,23.95) 54.45,27.9
  CONDUCTIVE3 w0.8: v2(54.45,23.95) 54.45,21.55 60.77,15.22 v1(68.53,15.22)
  BOTTOM w0.4: v1(76.5,51.8) 76.5,52.5 74,55 69.46,55 CN1.1
  BOTTOM w0.45: C14.2 v2(54.75,31.8) ; C13.2 v2(54.75,37.8) ; C12.2 v2(54.75,43.8)
  BOTTOM w0.65: CN1.1 67,51.4 R30.2
VMX: length 5.7
  TOP w0.65: VM.1 40,24.5 41.8,22.7 CN4.1
VREG: length 33.8
  TOP w0.3: 71.08,14 70.4,14 70,13.6 69.58,13.6 C5.2
  TOP w0.45: v1(70.4,9.72) R10.2 R9.2 ; SJP2.2 65.95,19.35 v1(66.35,19.75) ; v1(78.15,11.5) R12.2 R11.2 ; C5.2 69.47,13.01 v1(69.5,12.65)
  CONDUCTIVE3 w0.6: v1(78.15,11.5) 76.38,9.72 71.08,9.72 ; 71.08,9.72 70.4,10.4 ; 71.08,9.72 v1(70.4,9.72) 70.4,10.4 ; 70.4,10.4 69.5,11.3 v1(69.5,12.65)
  CONDUCTIVE3 w0.8: v1(66.35,19.75) TP1.1 68.5,18.2 70.4,16.3 70.4,13.55 v1(69.5,12.65)
  BOTTOM w0.4: R44.2 69.25,12.4 v1(69.5,12.65)
N73073: length 1.7
  TOP w0.2: 71.08,16.5 70.47,16.5 C4.1
N73078: length 3.1
  TOP w0.2: C4.2 68.78,16.8 68.88,16.7 69.7,16.7 70.4,16 71.08,16
N73366: length 2.6
  TOP w0.2: C7.2 R14.2 77.17,13.9 76.97,13.9 76.58,13.5 75.92,13.5
N87798: length 2.9
  TOP w0.6: Q1.4 v1(61.75,45.35)
  BOTTOM w0.2: R17.2 60.6,44.59 R18.2 v1(61.75,45.35)
N87832: length 2.9
  TOP w0.6: Q2.4 v1(61.75,39.35)
  BOTTOM w0.2: 61.75,39.35 R19.2 60.6,38.58 R15.2
N87866: length 2.9
  TOP w0.6: Q3.4 v1(61.75,33.35)
  BOTTOM w0.2: 61.75,33.35 R20.2 60.6,32.58 R16.2
N88470: length 2.7
  TOP w0.6: Q5.4 v1(73.75,40.6)
  BOTTOM w0.2: R22.2 74.51,39.61 R25.1 74.11,40.61 v1(73.75,40.6)
N88482: length 2.7
  TOP w0.6: Q6.4 v1(73.75,34.6)
  BOTTOM w0.2: v1(73.75,34.6) 74.11,34.61 R26.2 74.51,33.61 R23.2
N88708: length 2.7
  TOP w0.6: Q4.4 v1(73.75,46.6)
  BOTTOM w0.2: v1(73.75,46.6) 74.11,46.61 R24.2 74.51,45.6 R21.2
N99829: length 1.8
  TOP w0.2: 71.08,15.5 70.3,15.5 69.95,15.85 69.62,15.85 C2.1
N100688: length 1.5
  TOP w0.2: 75.92,13 76.72,13 76.83,13.1 77.3,13.1 R13.1
N145122: length 1.4
  TOP w0.2: SJP1.2 65.05,21.8 65.83,21.8 R1.1
N153811: length 9.5
  TOP w0.2: v1(18.3,21) R32.1 R35.2 ; 14.25,26.25 v1(15.75,26.25)
  BOTTOM w0.2: v1(15.75,26.25) 15.99,25.98 18.3,23.67 v1(18.3,21)
N153813: length 6.4
  TOP w0.2: SW2.2 v1(15.8,23.73) ; R34.2 R33.1 v1(14.8,21)
  BOTTOM w0.2: v1(15.8,23.73) 15.8,22 v1(14.8,21)
N153829: length 2
  TOP w0.2: R36.1 C11.2 R37.2
N153845: length 9.1
  TOP w0.2: R38.2 R39.2 18.75,11.03 SW4.1
  BOTTOM w0.2: SW4.1 SW4.2
N153865: length 16
  TOP w0.2: R41.2 v1(35.6,24.75)
  BOTTOM w0.2: v1(35.6,24.75) 36.1,24.25 36.1,12.85 VR1.2
N153867: length 2.3
  TOP w0.2: R41.1 33.77,24.75 JP1.1
N157910: length 4.3
  TOP w0.2: v1(65.75,11.8) 65.3,11.35 64.7,11.35 SJP4.1
  BOTTOM w0.4: R44.1 66.35,12.4 v1(65.75,11.8) 64.9,11.8 R5.2
N213336: length 4.9
  TOP w0.2: SW3.2 25.85,12.9 R36.2
N213555: length 1.4
  TOP w0.4: R3.1 76.85,49.67 DS1.1
N213849: length 1.3
  TOP w0.2: R42.1 25.52,23.65 DS3.1
N213908: length 1.3
  TOP w0.2: DS4.1 25.52,26.4 R43.1
N228706: length 6.2
  BOTTOM w0.3: IC2.1 64.25,47.4 64.05,47.2 62.55,47.2 62.35,47.4 IC2.3
  BOTTOM w0.65: IC2.1 C9.2 R30.1
N228786: length 2.4
  TOP w0.4: 77.75,55.02 77.08,55.7 v1(76.5,55.7)
  BOTTOM w0.4: v1(76.5,55.7) R31.1

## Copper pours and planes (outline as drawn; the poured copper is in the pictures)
GND on TOP: outline of 83 points within 52,9 75.37,27.19
GND on TOP: 60,55.15 59.63,55.08 59.29,54.86 59.08,54.54 59,54.15 59,52.9 58.97,52.83 58.9,52.8 52.38,52.8 52.33,52.81 52.24,52.86 52.06,53.04 52.03,53.08 52,53.18 52,56.66 52.01,56.7 52.03,56.73 52.27,56.97 52.3,56.99 52.34,57 78.76,57 78.8,56.99 78.83,56.97 79.27,56.53 79.29,56.5 79.3,56.46 79.3,53.72 79.29,53.69 79,52 79.29,50.31 79.3,50.28 79.3,47.83 79.28,47.75 79.24,47.68 79.03,47.47 79,47.45 78.96,47.44 76.8,47.44 76.75,47.44 76.66,47.43 75.44,47.43 75.34,47.42 75.21,47.4 69.86,47.4 69.82,47.41 69.79,47.43 69.54,47.67 69.52,47.7 69.51,47.74 69.51,54.45 69.31,54.94 68.81,55.15 ; 2 cut-outs
GND on TOP: outline of 251 points within 55.1,9 89,28.12 ; 1 cut-out
GND on BOTTOM: 65.42,28.07 65.45,28.09 65.5,28.1 70.66,28.1 70.7,28.09 70.73,28.07 70.97,27.83 70.99,27.8 71,27.76 71,20.14 70.99,20.1 70.97,20.07 70.96,20.06 70.89,20.02 70.82,20 70.7,20 70.26,19.73 70.29,19.22 70.38,19.07 70.4,19.02 70.4,18.47 70.39,18.43 70.37,18.39 70.31,18.33 70.27,18.31 70.23,18.3 66.77,18.3 64.8,20.27 64.8,27.37 64.82,27.44 64.86,27.51 ; 3 cut-outs
GND on BOTTOM: 66.77,13.95 66.73,13.96 66.69,13.98 66.06,14.61 65.96,14.68 65.85,14.7 62,14.7 61.6,15.1 61.6,18.5 61.63,18.57 61.7,18.6 62,18.6 62.02,18.6 62.07,18.6 62.1,18.57 65.04,15.64 65.14,15.57 65.25,15.55 67.92,15.55 68,15.52 68.03,15.45 68.03,15.23 68.52,14.72 69.03,15.22 69.03,15.45 69.05,15.52 69.12,15.55 69.33,15.55 69.37,15.54 69.41,15.52 70.57,14.36 70.59,14.32 70.6,14.28 70.6,14.05 70.57,13.98 70.5,13.95
GND on BOTTOM: outline of 112 points within 52,9 89,57 ; 8 cut-outs
GND on CONDUCTIVE2: 62.6,28.6 62.86,27.96 63.5,27.7 64.91,27.7 64.98,27.72 65.05,27.76 65.36,28.07 65.43,28.11 65.5,28.13 72.73,28.13 72.8,28.11 72.87,28.07 73.36,27.58 73.38,27.55 73.39,27.51 73.39,25.5 73.89,25 88.46,25 88.5,24.99 88.53,24.97 88.94,24.56 88.98,24.49 89,24.42 89,10 88.71,9.29 88,9 52.54,9 52.5,9.01 52.47,9.03 52.03,9.47 52.01,9.5 52,9.54 52,22.3 52,22.34 52,56.46 52.01,56.5 52.03,56.53 52.47,56.97 52.51,56.99 52.55,57 78.76,57 78.8,56.99 78.83,56.97 79.27,56.53 79.29,56.5 79.3,56.46 79.3,47.94 79.29,47.9 79.27,47.87 78.83,47.43 78.8,47.41 78.76,47.4 73.45,47.4 73.11,47.06 73.04,47.02 72.97,47 65.78,47 65.75,47 65.55,46.94 65.38,46.82 65.08,46.52 64.8,46.24 64.73,46.2 64.66,46.18 63.44,46.18 63.17,46.13 62.94,45.97 62.66,45.69 62.62,45.63 62.6,45.55 ; 31 cut-outs
GND on CONDUCTIVE3: 62.6,28.46 62.65,28.23 62.78,28.04 62.96,27.86 63.15,27.73 63.38,27.68 64.89,27.68 64.96,27.7 65.03,27.74 65.36,28.07 65.43,28.11 65.5,28.13 66.36,28.13 66.39,28.13 72.73,28.13 72.8,28.12 72.87,28.07 73.36,27.58 73.38,27.55 73.39,27.51 73.39,25.5 73.89,25 88.46,25 88.5,24.99 88.53,24.97 88.94,24.56 88.98,24.49 89,24.42 89,10 88.71,9.29 88,9 52.54,9 52.5,9.01 52.47,9.03 52.03,9.47 52.01,9.5 52,9.54 52,22.3 52,22.34 52,56.46 52.01,56.5 52.03,56.53 52.47,56.97 52.51,56.99 52.55,57 78.76,57 78.8,56.99 78.83,56.97 79.27,56.53 79.29,56.5 79.3,56.46 79.3,47.94 79.29,47.9 79.27,47.87 78.83,47.43 78.8,47.41 78.76,47.4 73.45,47.4 73.11,47.06 73.04,47.02 72.97,47 65.78,47 65.75,47 65.55,46.94 65.38,46.82 65.08,46.52 64.8,46.24 64.73,46.2 64.66,46.18 63.44,46.18 63.17,46.13 62.94,45.97 62.66,45.69 62.62,45.63 62.6,45.55 ; 21 cut-outs
GNDX on TOP: 9.03,9.27 9.01,9.3 9,9.34 9,9.95 9.01,9.99 9.03,10.02 9.04,10.03 9.58,17.49 2.12,17.15 2.11,17.14 2.08,17.12 2.04,17.11 1.34,17.11 1.3,17.12 1.27,17.14 1.03,17.38 1.01,17.41 1,17.45 1,48.16 1.01,48.2 1.03,48.23 1.27,48.47 1.3,48.49 1.34,48.5 2.39,48.5 2.43,48.49 2.46,48.47 4.02,47.41 5.86,47 5.92,46.97 5.95,46.91 6.29,46.23 7,45.95 7.04,45.95 9.5,45.95 9.5,45.95 10.27,46.24 10.59,47 10.59,50 10.6,50.04 10.87,53.11 9.29,55.77 9.06,56 9.02,56.06 9,56.14 9,56.66 9.01,56.7 9.03,56.73 9.27,56.97 9.3,56.99 9.34,57 49.46,57 49.5,56.99 49.53,56.97 49.97,56.53 49.99,56.5 50,56.46 50,9.54 49.99,9.5 49.97,9.47 49.53,9.03 49.5,9.01 49.46,9 9.34,9 9.3,9.01 9.27,9.03 ; 72 cut-outs
GNDX on CONDUCTIVE2: 1,56 1.29,56.71 2,57 49.46,57 49.5,56.99 49.53,56.97 49.97,56.53 49.99,56.5 50,56.46 50,9.54 49.99,9.5 49.97,9.47 49.53,9.03 49.5,9.01 49.46,9 2,9 1.29,9.29 1,10 ; 98 cut-outs
GNDX on CONDUCTIVE3: 1,56 1.29,56.71 2,57 49.46,57 49.5,56.99 49.53,56.97 49.97,56.53 49.99,56.5 50,56.46 50,9.54 49.99,9.5 49.97,9.47 49.53,9.03 49.5,9.01 49.46,9 2,9 1.29,9.29 1,10 ; 86 cut-outs
Net_1 on BOTTOM: 50,1 1,1 1,6 50,6 ; 2 cut-outs
Net_2 on BOTTOM: 89,1 52,1 52,6 89,6 ; 2 cut-outs
Net_3 on BOTTOM: 4.5,3.5 5.5,3.5
Net_4 on BOTTOM: 6.5,3.5 7.5,3.5
Net_5 on BOTTOM: 82,3.5 83,3.5
Net_6 on BOTTOM: 84,3.5 85,3.5
Net_7 on BOTTOM: 50,60 1,60 1,65 50,65 ; 2 cut-outs
Net_8 on BOTTOM: 89,60 52,60 52,65 89,65 ; 2 cut-outs
Net_9 on BOTTOM: 4.5,62.5 5.5,62.5
Net_10 on BOTTOM: 6.5,62.5 7.5,62.5
Net_11 on BOTTOM: 82.5,62.5 83.5,62.5
Net_12 on BOTTOM: 84.5,62.5 85.5,62.5
Net_13 on CONDUCTIVE3: 50,1 1,1 1,6 50,6 ; 1 cut-out
Net_14 on CONDUCTIVE3: 89,1 52,1 52,6 89,6 ; 1 cut-out
Net_15 on CONDUCTIVE3: 50,60 1,60 1,65 50,65 ; 1 cut-out
Net_16 on CONDUCTIVE3: 89,60 52,60 52,65 89,65 ; 1 cut-out
Net_17 on CONDUCTIVE2: 50,1 1,1 1,6 50,6 ; 1 cut-out
Net_18 on CONDUCTIVE2: 89,1 52,1 52,6 89,6 ; 1 cut-out
Net_19 on CONDUCTIVE2: 50,60 1,60 1,65 50,65 ; 1 cut-out
Net_20 on CONDUCTIVE2: 89,60 52,60 52,65 89,65 ; 1 cut-out
Net_21 on TOP: 50,1 1,1 1,6 50,6 ; 2 cut-outs
Net_22 on TOP: 89,1 52,1 52,6 89,6 ; 2 cut-outs
Net_23 on TOP: 4.5,3.5 5.5,3.5
Net_24 on TOP: 6.5,3.5 7.5,3.5
Net_25 on TOP: 82,3.5 83,3.5
Net_26 on TOP: 84,3.5 85,3.5
Net_27 on TOP: 50,60 1,60 1,65 50,65 ; 2 cut-outs
Net_28 on TOP: 89,60 52,60 52,65 89,65 ; 2 cut-outs
Net_29 on TOP: 4.5,62.5 5.5,62.5
Net_30 on TOP: 6.5,62.5 7.5,62.5
Net_31 on TOP: 82.5,62.5 83.5,62.5
Net_32 on TOP: 84.5,62.5 85.5,62.5
OUTU on TOP: 61.23,40.18 61.12,40.21 61.05,40.28 61.02,40.38 61.02,43.35 61.05,43.45 61.12,43.52 61.23,43.55 62.71,43.55 62.81,43.58 62.85,43.61 62.92,43.68 62.97,43.77 62.98,43.82 62.98,45.22 62.98,45.27 63.03,45.36 63.3,45.62 63.34,45.65 63.44,45.68 64.66,45.68 65.01,45.77 65.15,45.88 65.4,46.14 65.74,46.47 65.77,46.49 65.81,46.5 72.12,46.5 72.13,46.5 72.26,46.44 72.32,46.3 72.32,41.1 72.29,41.03 72.22,41 65.64,41 65.54,40.97 65.5,40.94 65.06,40.5 65.05,40.49 64.8,40.24 64.76,40.21 64.66,40.18
OUTU on CONDUCTIVE3: 63.38,40.18 63.34,40.19 63.31,40.21 63.13,40.39 63.11,40.42 63.1,40.46 63.1,45.38 63.11,45.42 63.13,45.45 63.3,45.62 63.44,45.68 64.66,45.68 65.01,45.77 65.15,45.88 65.4,46.14 65.74,46.47 65.76,46.49 65.81,46.5 73.18,46.5 73.24,46.48 73.28,46.43 73.75,46.1 74.22,46.43 74.26,46.48 74.32,46.5 75.67,46.5 75.73,46.48 75.76,46.44 76.23,46.12 76.69,46.44 76.73,46.48 76.79,46.5 80.96,46.5 81.04,46.52 81.1,46.56 82.47,47.93 82.54,47.97 82.61,47.99 86.34,47.99 86.42,47.96 86.86,47.52 86.89,47.45 86.89,41.54 86.86,41.47 86.42,41.03 86.34,41 76.59,41 76.56,41.01 76.53,41.02 76.23,41.12 75.93,41.02 75.9,41.01 75.87,41 74.08,41 74.05,41 74.03,41.02 73.75,41.1 73.47,41.02 73.45,41 73.42,41 65.64,41 65.56,40.98 65.5,40.94 65.05,40.49 64.73,40.2 64.66,40.18
OUTV on TOP: 61.23,34.18 61.12,34.21 61.05,34.28 61.02,34.38 61.02,37.35 61.05,37.45 61.12,37.52 61.23,37.55 62.71,37.55 62.81,37.58 62.85,37.61 62.92,37.68 62.97,37.77 62.98,37.82 62.98,39.22 62.98,39.27 63.03,39.36 63.3,39.62 63.34,39.65 63.44,39.68 64.66,39.68 65.01,39.77 65.15,39.89 65.4,40.14 65.74,40.47 65.77,40.49 65.81,40.5 72.12,40.5 72.13,40.5 72.26,40.44 72.32,40.3 72.32,35.1 72.29,35.03 72.22,35 65.64,35 65.54,34.97 65.5,34.94 65.06,34.5 65.05,34.49 64.8,34.24 64.76,34.21 64.66,34.18
OUTV on CONDUCTIVE3: 82.55,33.25 82.47,33.27 82.41,33.31 80.78,34.94 80.71,34.98 80.63,35 76.59,35 76.56,35.01 76.53,35.02 76.23,35.12 75.93,35.02 75.9,35.01 75.87,35 74.08,35 74.05,35 74.03,35.02 73.75,35.1 73.47,35.02 73.45,35 73.42,35 65.64,35 65.56,34.98 65.5,34.94 65.06,34.5 65.05,34.49 64.8,34.24 64.73,34.2 64.66,34.18 63.35,34.18 63.31,34.19 63.28,34.21 63.13,34.36 63.11,34.39 63.1,34.43 63.1,39.38 63.11,39.42 63.13,39.45 63.3,39.62 63.36,39.66 63.44,39.68 64.66,39.68 64.93,39.73 65.15,39.89 65.4,40.14 65.74,40.47 65.77,40.49 65.81,40.5 73.18,40.5 73.24,40.48 73.28,40.43 73.75,40.1 74.22,40.43 74.26,40.48 74.32,40.5 75.67,40.5 75.73,40.48 75.76,40.44 76.23,40.12 76.69,40.44 76.73,40.48 76.79,40.5 86.34,40.5 86.42,40.47 86.86,40.03 86.89,39.96 86.89,33.79 86.86,33.72 86.42,33.28 86.34,33.25
OUTW on TOP: 61.23,28.18 61.12,28.21 61.05,28.28 61.02,28.38 61.02,31.35 61.05,31.45 61.12,31.52 61.23,31.55 62.71,31.55 62.81,31.58 62.85,31.61 62.92,31.68 62.97,31.77 62.98,31.82 62.98,33.22 62.98,33.27 63.03,33.36 63.3,33.62 63.34,33.65 63.44,33.68 64.66,33.68 65.01,33.77 65.15,33.89 65.4,34.14 65.74,34.47 65.77,34.49 65.81,34.5 72.12,34.5 72.13,34.5 72.26,34.44 72.32,34.3 72.32,29.39 72.31,29.35 72.29,29.32 72.03,29.06 71.99,29.03 71.89,29 65.64,29 65.54,28.97 65.5,28.94 65.06,28.5 65.05,28.49 64.8,28.24 64.76,28.21 64.66,28.18
OUTW on CONDUCTIVE3: 81.25,25.63 81.18,25.65 81.11,25.69 77.81,28.99 77.8,29 65.64,29 65.56,28.98 65.5,28.94 65.06,28.5 65.05,28.49 64.8,28.24 64.73,28.2 64.66,28.18 63.38,28.18 63.34,28.19 63.31,28.21 63.13,28.39 63.11,28.42 63.1,28.46 63.1,33.38 63.11,33.42 63.13,33.45 63.3,33.62 63.36,33.66 63.44,33.68 64.66,33.68 64.93,33.73 65.15,33.89 65.4,34.14 65.74,34.47 65.77,34.49 65.81,34.5 73.18,34.5 73.24,34.48 73.28,34.43 73.75,34.1 74.22,34.43 74.26,34.48 74.32,34.5 75.67,34.5 75.73,34.48 75.76,34.44 76.23,34.12 76.69,34.44 76.73,34.48 76.79,34.5 80.47,34.5 80.51,34.49 80.54,34.47 82.05,32.95 82.28,32.8 82.55,32.75 86.34,32.75 86.42,32.72 86.86,32.28 86.89,32.21 86.89,26.17 86.86,26.1 86.42,25.66 86.34,25.63
RSA on TOP: outline of 90 points within 73.03,21.23 80.4,46.94
VLDOX on CONDUCTIVE3 (solid shape): 12.01,17.76 12.52,18 13.58,17.63 13.85,17.25 13.58,16.87 12.52,16.5 12.45,16.48 12.38,16.47 12.1,16.59 11.98,16.87 12.06,17.1 12.25,17.25
VLDOX on CONDUCTIVE3 (solid shape): 18.51,17.76 19.02,18 20.08,17.63 20.35,17.25 20.08,16.87 19.02,16.5 18.95,16.48 18.88,16.47 18.6,16.59 18.48,16.87 18.56,17.1 18.75,17.25
VM on TOP: 65.81,47 65.58,46.95 65.38,46.82 65.08,46.52 64.8,46.24 64.73,46.2 64.66,46.18 61.78,46.18 61.75,46.16 61.71,46.15 61.19,45.92 60.95,45.39 60.93,45.34 60.88,45.3 60.62,45.11 60.52,44.8 60.52,28.15 60.51,28.07 60.47,28.01 60.21,27.75 60.14,27.71 60.07,27.69 52.29,27.69 52.25,27.7 52.22,27.72 52.06,27.88 52.02,27.95 52,28.02 52,51.96 52.01,52 52.03,52.03 52.27,52.27 52.3,52.29 52.34,52.3 58.98,52.3 59.35,52.45 59.5,52.83 59.5,54.26 59.51,54.3 59.53,54.33 59.77,54.57 59.8,54.59 59.84,54.6 68.67,54.6 68.71,54.59 68.74,54.57 68.99,54.33 69.01,54.3 69.01,54.26 69.01,47.34 69.01,47.3 68.99,47.27 68.74,47.03 68.71,47.01 68.67,47 ; 7 cut-outs

Small or netless copper shapes (teardrops, artwork), in the pictures only: 104 on TOP, 104 on BOTTOM, 9 on CONDUCTIVE3

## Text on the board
Ref Des/Silkscreen Bottom: IC2 | C10 | R44 | R31 | R24 | R25 | R26 | C12 | C13 | C14 | R15 | R16 | R17 | R18 | R19 | R20 | R5 | C9 | R30 | R21 | R22 | R23
Ref Des/Silkscreen Top: CN5 | CN7 | 1 | R29 | R28 | R33 | R34 | R38 | 3 | R35 | R39 | R32 | R42 | R43 | C11 | R36 | R37 | DS4 | DS3 | 0V | JP1 | R41 | 6 | 5V | 15 | 4 | SJP | 8 | C8 | 5 | 2 | 7 | VREG | TC78B011FTG | C2 | C5 | C4 | TP1 | IC1 | R27 | R11 | R12 | SCL | SDA | GND | STBY | SEL | CWCCW | BRAKE | SPD | ALERT | FG | CMO | 16 | Q1 | Q2 | Q3 | R10 | C1 | R1 | C3 | R9 | Q6 | Q4 | Q5 | DS2 | R3 | DS1 | R14 | R13 | C7 | C6 | ON | ID2 | ID1 | Analog/PWM | SW1 | CN9 | SW4 | SW2 | Normal | I2C | H | L | CN6 | POT Cut | VM | CN8 | CN4 | CN2 | CN1 | (Push-H) | SW3 | VR1 | CN3 | VLDO | Sensorless Sinusoidal Drive MCD RM | W | U | V | USB | USB-I2C Converter
